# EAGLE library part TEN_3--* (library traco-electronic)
DC/DC Konverter 3 Watt, 2 x Input, 2 x Output Source: http://www.tracopower.com/datasheet_g/ten3-d.pdf
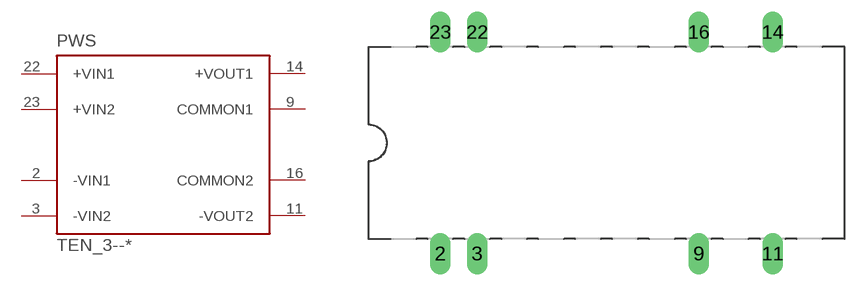
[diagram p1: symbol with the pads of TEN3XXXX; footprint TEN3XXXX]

Designator prefix PWS

## TEN_3--122 (OC_FARNELL: unknown; OC_NEWARK: unknown), TEN_3--0521 (OC_FARNELL: unknown; OC_NEWARK: unknown), TEN_3--0522 (MPN: TEN 3-0522; OC_FARNELL: unknown; OC_NEWARK: 91R2128), TEN_3--0523 (OC_FARNELL: unknown; OC_NEWARK: unknown), TEN_3--1221 (MPN: TEN31221; OC_FARNELL: unknown; OC_NEWARK: 60R5780), TEN_3--1223 (OC_FARNELL: unknown; OC_NEWARK: unknown), TEN_3--2421 (OC_FARNELL: unknown; OC_NEWARK: unknown), TEN_3--2422 (MPN: TEN 3-2422WI; OC_FARNELL: unknown; OC_NEWARK: 78R5872), TEN_3--2423 (MPN: TEN3-2423; OC_FARNELL: unknown; OC_NEWARK: 72J5373), TEN_3--4821 (OC_FARNELL: unknown; OC_NEWARK: unknown), TEN_3--4822 (OC_FARNELL: unknown; OC_NEWARK: unknown), TEN_3--4823 (OC_FARNELL: unknown; OC_NEWARK: unknown)  [TEN3XXXX]
2  -VIN1  in
3  -VIN2  in
9  COMMON1  pas
11  -VOUT2  pas
14  +VOUT1  pas
16  COMMON2  pas
22  +VIN1  in
23  +VIN2  in

## Footprint TEN3XXXX (pad centres in mm)
DC/DC Konverter 3 Watt Source: http://www.tracopower.com/datasheet_g/ten3-d.pdf
drill 0.813 pad 1.422 long: 2 -11.43,-7.62; 3 -8.89,-7.62; 9 6.35,-7.62; 11 11.43,-7.62; 14 11.43,7.62; 16 6.35,7.62; 22 -8.89,7.62; 23 -11.43,7.62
